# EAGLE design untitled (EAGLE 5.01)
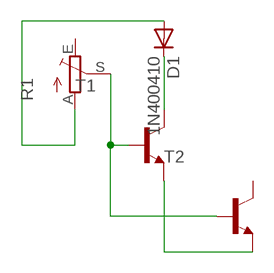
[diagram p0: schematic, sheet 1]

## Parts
D1  1N400410  [DO41-10]
R1  TRIM_EU-LI15  [LI15]
T1  BC337-NPN-TO92-EBC  [TO92-EBC]
T2  BC337-NPN-TO92-EBC  [TO92-EBC]

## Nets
N$1: D1.A R1.A
N$2: R1.S T1.B T2.B
N$3: D1.C T1.C
N$4: T1.E T2.E
Unconnected: R1.E T2.C

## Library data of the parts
D1 = diode-1:1N4004: DIODE
R1 = pot:TRIM_EU-: POTENTIOMETER
T1 T2 = transistor:*-NPN-: NPN Transistror BF959 corrected 2008.03.06

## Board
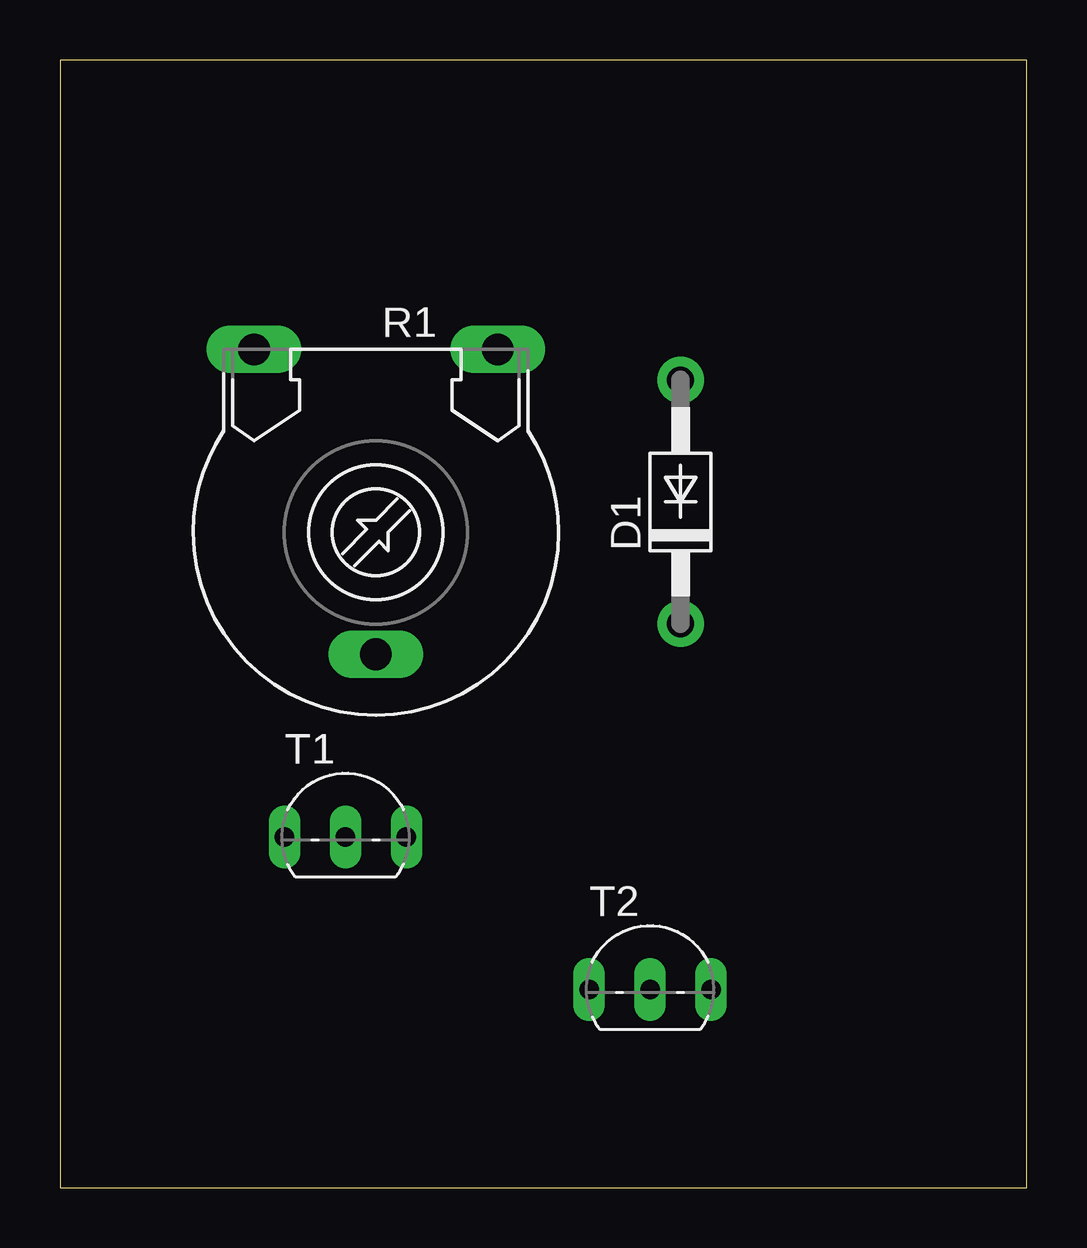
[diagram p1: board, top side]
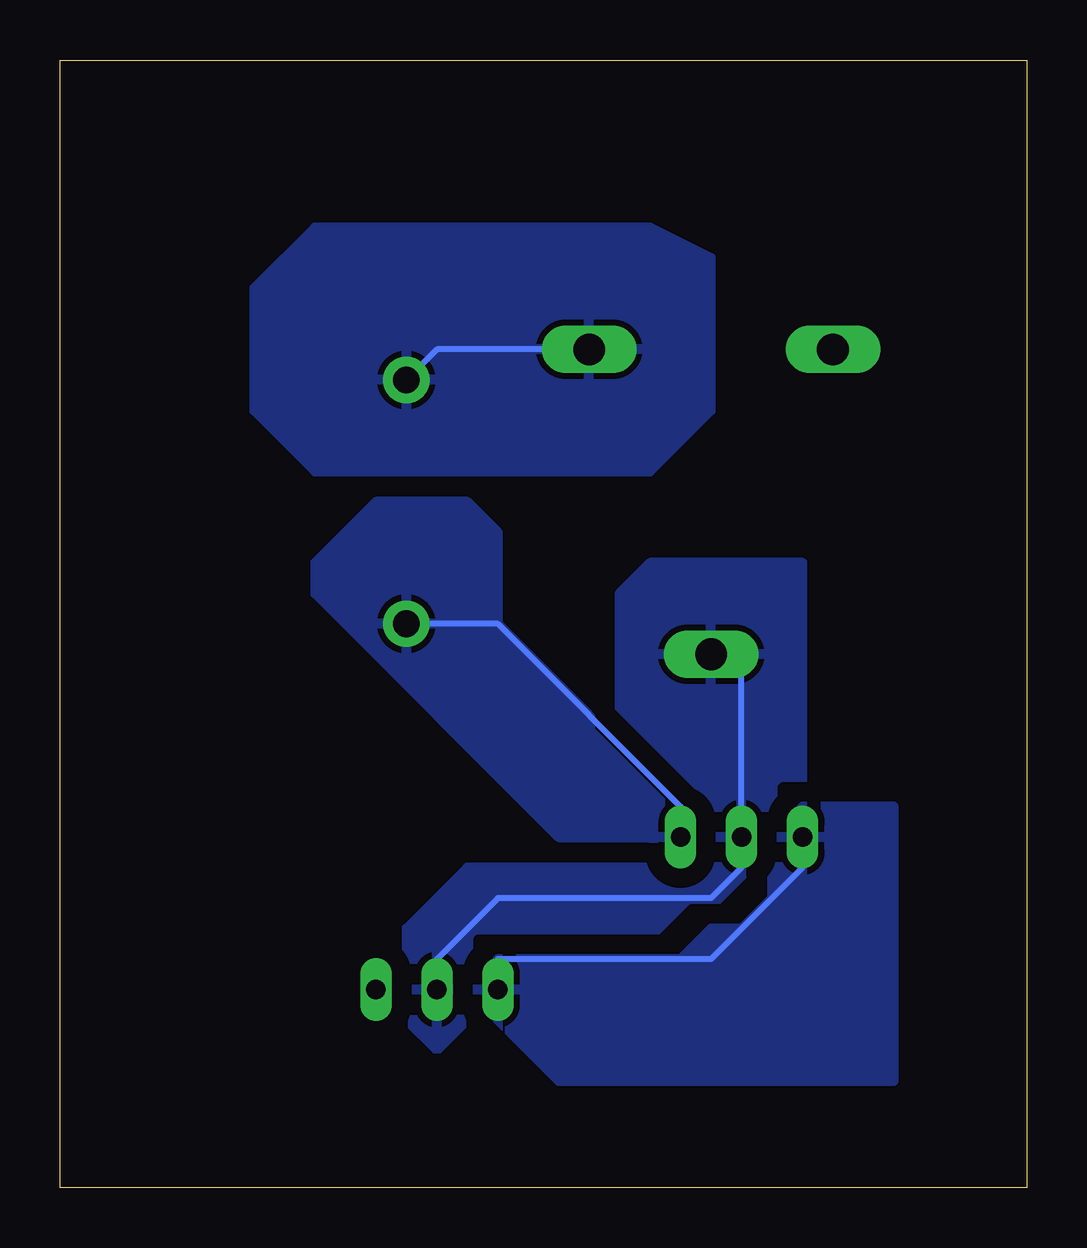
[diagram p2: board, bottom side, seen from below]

Size 40.31 x 46.98 mm. Coordinates in mm from the lower left corner, seen from the top.
Outline: 0,0 40.31,0 40.31,46.98 0,46.98 0,0
Copper layers (1*16): Top 0.035mm / dielectric 1.5mm / Bottom 0.035mm
Design rules "default": minimum track width 10mil, minimum drill 24mil, track to track 8mil, track to pad 8mil, pad to pad 8mil, via to via 8mil, smd to smd 8mil, copper to edge 40mil, drill to drill 8mil, minimum pad ring 10mil, minimum via ring 8mil, stop-mask expansion 4mil, vias tented up to drill 0mil, thermal gap 10mil

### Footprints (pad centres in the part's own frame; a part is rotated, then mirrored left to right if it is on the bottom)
DO41-10 = drill 1.118 pad 1.93 round: A 5.08,0; C -5.08,0
LI15 = drill 1.321 long: A -5.08,-7.62; E 5.08,-7.62; S 0,5.08
TO92-EBC = drill 0.813 long: B 0,-1.27; C 2.54,-1.27; E -2.54,-1.27

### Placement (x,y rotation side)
D1  25.87,28.57 90 top
R1  13.17,27.3 180 top
T1  11.9,15.87 0 top
T2  24.6,9.52 0 top

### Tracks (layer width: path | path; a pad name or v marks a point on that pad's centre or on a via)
N$1
  Bottom 0.254: D1.A 24.6,34.92 R1.A
  pour Bottom (isolate 0.813, rank 4): 15.71,40 29.68,40 32.22,37.46 32.22,32.38 29.68,29.84 15.71,29.84 13.17,32.38 13.17,38.73
N$2
  Bottom 0.254: R1.S 11.9,22.22 T1.B 11.9,13.33 13.17,12.06 22.06,12.06 24.6,9.52 T2.B
  pour Bottom (isolate 0.813, rank 2): 9.36,26.03 15.71,26.03 16.98,24.76 16.98,19.68 13.17,15.87 13.17,14.6 14.44,13.33 23.33,13.33 25.87,10.79 25.87,6.98 24.6,5.71 20.79,9.52 13.17,9.52 9.36,13.33
N$3
  Bottom 0.254: D1.C 22.06,23.49 14.44,15.87 T1.C
  pour Bottom (isolate 0.813, rank 3): 13.17,15.87 14.44,15.87 22.06,23.49 22.06,27.3 23.33,28.57 27.14,28.57 29.68,26.03 29.68,24.76 19.52,14.6 15.71,14.6 14.44,13.33 13.17,13.33
N$4
  Bottom 0.254: T1.E 9.36,13.33 13.17,9.52 22.06,9.52 T2.E
  pour Bottom (isolate 0.813): 5.55,15.87 9.36,15.87 10.63,14.6 10.63,12.06 11.9,10.79 13.17,10.79 14.44,9.52 22.06,9.52 23.33,8.25 19.52,4.44 5.55,4.44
